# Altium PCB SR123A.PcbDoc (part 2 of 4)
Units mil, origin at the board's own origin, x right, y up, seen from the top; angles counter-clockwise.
Board outline 5500 x 3200 mil, 4 copper layers (Top Layer, Signal Layer 1, Signal Layer 2, Bottom Layer), stack 64.312 mil thick; 295 components, 105 nets, 659 pads, 1365 vias.
Unrouted connection lines stored in the file: 735.
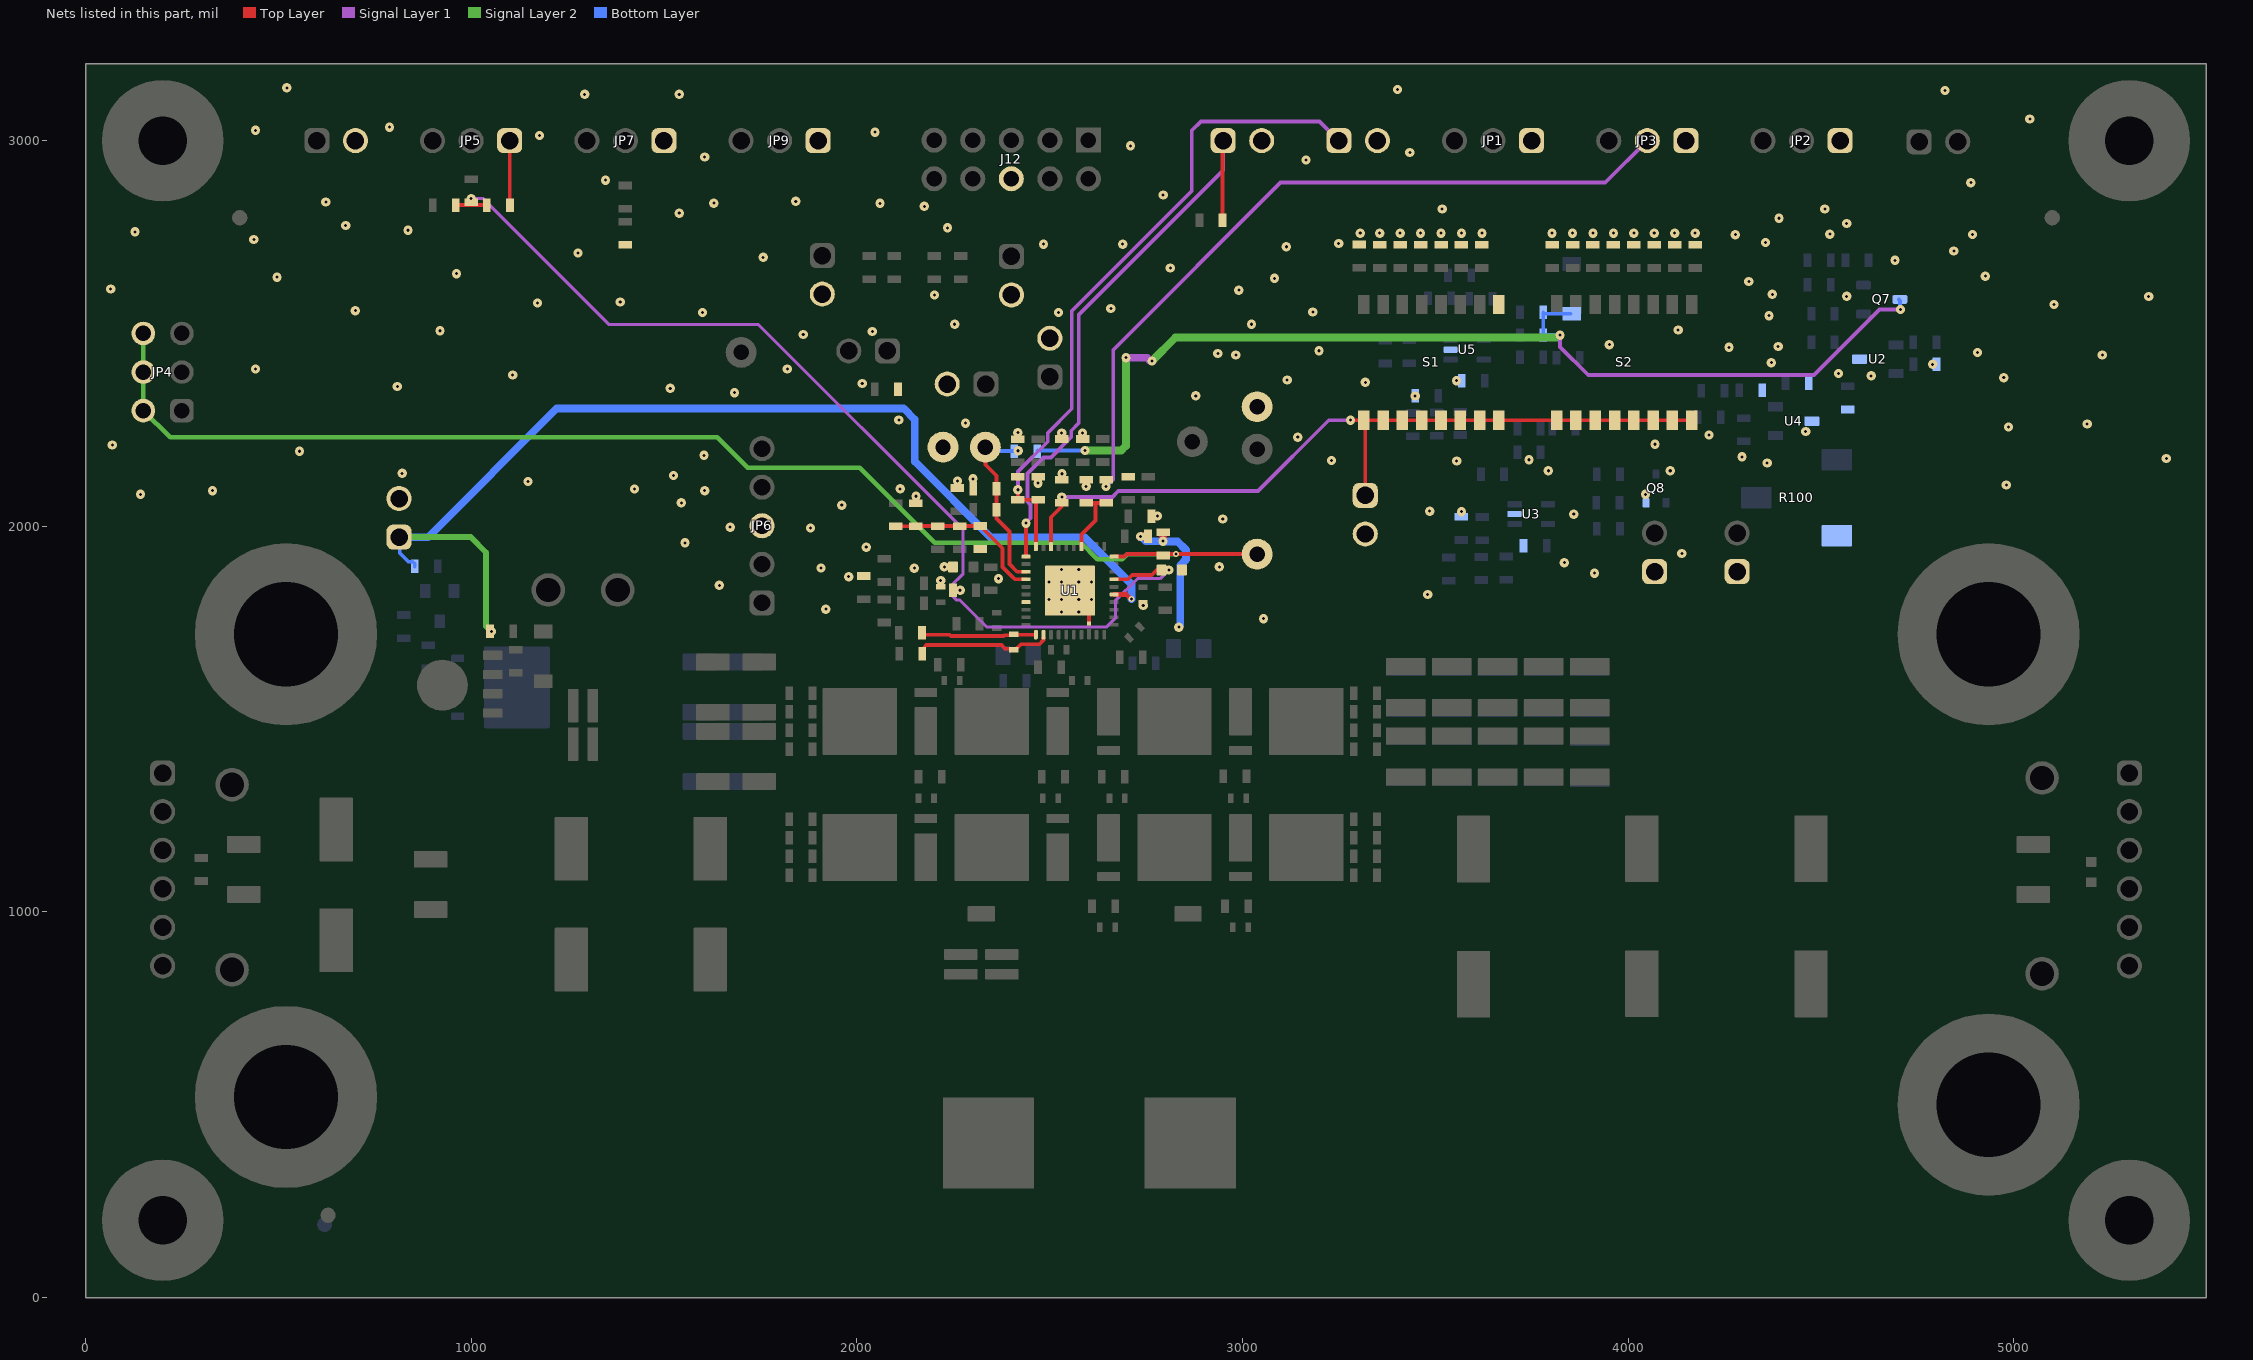
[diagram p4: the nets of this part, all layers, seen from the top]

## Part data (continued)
C27 C28 C29: library part CMP-0097021-1, "120 µF 50 V Aluminum - Polymer Capacitors Radial, Can - SMD 24mOhm 2000 Hrs @ 125°C", Digikey Part Number=399-A768MS127M1HLAE024CT-ND, Leakage Current=1200uA, Manufacturer=KEMET, Mouser Part Number=80-A768MS127M1HLAE24, Operating Temperature Range="-55°C to +125°C", Tolerance_%=20%, ValueDisplayed=120uF
C33 C46 C47: library part CMP-0086535-1, "0.1µF ±10% 50V Ceramic Capacitor X8L 0603 (1608 Metric)", Manufacturer="Murata Electronics North America", TempCo=-40+15%, Tolerance_%=10%
C34 C35: library part CMP-0006618-2, "CAP, CERM, 0.1 uF, 100 V, +/- 10%, X5R, 0402", Cap_Case=0402, Manufacturer=MuRata, Supplier Part Number 1=490-10458-1-ND, TempCo=X5R, Tolerance_%=10%, Value1=Unknown, Value2=100V, ValueDisplayed=0.1uF
C36: library part CMP-0007099-4, "CAP, CERM, 0.1 uF, 100 V, +/- 10%, X7S, AEC-Q200 Grade 1, 0603", Cap_Case=0603, Manufacturer=TDK, Supplier Part Number 1=445-6938-1-ND, TempCo=X7S, Tolerance_%=10%, Value1="0.04959 ohm", Value2=100V, ValueDisplayed=0.1uF
C37 C38: library part CMP-0092433-2, "Multi-Layer Ceramic Capacitor 22uF 10V X5R ±20% 0603 Paper T/R", Manufacturer=Murata, Operating Temperature Range="-55°C to +85°C", TempCo=15%, Temperature Characteristic=X5R, Tolerance_%=20%, ValueDisplayed=22uF
C39 C40: library part CMP-0006356-2, "CAP, CERM, 0.1 uF, 50 V, +/- 10%, X7R, AEC-Q200 Grade 1, 0402", Cap_Case=0402, Manufacturer=MuRata, Supplier Part Number 1=490-10672-1-ND, TempCo=X7R, Tolerance_%=10%, Value1=Unknown, Value2=50V, ValueDisplayed=0.1uF
C41: library part CMP-0006792-4, "CAP, CERM, 56 pF, 50 V, +/- 1%, C0G/NP0, 0603", Cap_Case=0603, Manufacturer=AVX, Supplier Part Number 1=478-7922-1-ND, TempCo=C0G/NP0, Tolerance_%=1%, Value1=Unknown, Value2=50V, ValueDisplayed=56pF
C42: library part CMP-0006984-4, "CAP, CERM, 0.022 uF, 50 V, +/- 10%, X7R, 0603", Cap_Case=0603, Manufacturer=Kemet, Supplier Part Number 1=399-5340-1-ND, TempCo=X7R, Tolerance_%=10%, Value1=Unknown, Value2=50V, ValueDisplayed=0.022uF
C43: library part CMP-0006793-4, "CAP, CERM, 56 pF, 50 V, +/- 5%, C0G/NP0, 0603", Cap_Case=0603, Manufacturer=AVX, Supplier Part Number 1=478-1172-1-ND, TempCo=C0G/NP0, Tolerance_%=5%, Value1="0.159 ohm", Value2=50V, ValueDisplayed=56pF
C44: library part CMP-0006806-4, "CAP, CERM, 0.033 uF, 50 V, +/- 5%, X7R, 0603", Cap_Case=0603, Manufacturer=AVX, Supplier Part Number 1=478-3723-1-ND, TempCo=X7R, Tolerance_%=5%, Value1=Unknown, Value2=50V, ValueDisplayed=0.033uF
C45: library part CMP-0007117-4, "CAP, CERM, 33 pF, 50 V, +/- 5%, C0G/NP0, 0603", Cap_Case=0603, Manufacturer="Samsung Electro-Mechanics", Supplier Part Number 1=1276-2262-1-ND, TempCo=C0G/NP0, Tolerance_%=5%, Value1=Unknown, Value2=50V, ValueDisplayed=33pF
C48: library part CMP-0006410-2, "CAP, CERM, 100 pF, 50 V, +/- 5%, C0G/NP0, 0402", Cap_Case=0402, Manufacturer=MuRata, Supplier Part Number 1=81-GRM1555C1H101JA1D, TempCo=C0G/NP0, Tolerance_%=5%, Value1=Unknown, Value2=50V, ValueDisplayed=100pF
C49: library part CMP-0860983-1, "CAP, CERM, 0.1 µF, 50 V,+/- 10%, X7R, 0402", Cap_Case=0402, Manufacturer="Passive Plus", TempCo=X7R, Tolerance_%=10%, Value2=50V, ValueDisplayed=0.1µF
C50: library part CMP-0007253-4, "CAP, CERM, 20 pF, 100 V, +/- 5%, C0G/NP0, 0603", Cap_Case=0603, Manufacturer=MuRata, Supplier Part Number 1=490-1334-1-ND, TempCo=C0G/NP0, Tolerance_%=5%, Value1=Unknown, Value2=100V, ValueDisplayed=20pF
C51: library part CMP-0007185-4, "CAP, CERM, 150 pF, 50 V, +/- 5%, C0G/NP0, 0603", Cap_Case=0603, Manufacturer=MuRata, Supplier Part Number 1=490-1431-1-ND, TempCo=C0G/NP0, Tolerance_%=5%, Value1=Unknown, Value2=50V, ValueDisplayed=150pF
C52 C53 C54: library part CMP-0006723-4, "CAP, CERM, 1000 pF, 100 V, +/- 5%, X7R, 0603", Cap_Case=0603, Manufacturer=AVX, Supplier Part Number 1=478-3698-1-ND, TempCo=X7R, Tolerance_%=5%, Value1="0.276 ohm", Value2=100V, ValueDisplayed=1000pF
C55 C56 C57 C61 C62 C63: library part CMP-0086096-1, "CAP, CERM, 680 pF, 50 V,+/- 1%, C0G/NP0, AEC-Q200 Grade 1, 0402", Cap_Case=0402, Manufacturer=MuRata, TempCo=C0G/NP0, Tolerance_%=1%, Value2=50V, ValueDisplayed=680pF
C58 C64: library part CMP-0006692-2, "CAP, CERM, 4700 pF, 50 V, +/- 10%, X7R, 0402", Cap_Case=0402, Manufacturer=MuRata, Supplier Part Number 1=490-1308-1-ND, TempCo=X7R, Tolerance_%=10%, Value1=Unknown, Value2=50V, ValueDisplayed=4700pF
C59: library part CMP-0008176-2, "CAP, CERM, 680 pF, 100 V, +/- 5%, C0G/NP0, 0805", Cap_Case=0805, Manufacturer=MuRata, Supplier Part Number 1=490-1613-1-ND, TempCo=C0G/NP0, Tolerance_%=5%, Value1=Unknown, Value2=100V, ValueDisplayed=680pF
C60: library part CMP-0008116-2, "CAP, CERM, 3000 pF, 100 V, +/- 5%, C0G/NP0, 0805", Cap_Case=0805, Manufacturer=MuRata, Supplier Part Number 1=GRM2165C2A302JA01D-ND, TempCo=C0G/NP0, Tolerance_%=5%, Value1=Unknown, Value2=100V, ValueDisplayed=3000pF
C89 C91 C95: library part CMP-0006889-4, "CAP, CERM, 0.018 uF, 100 V, +/- 10%, X7R, 0603", Cap_Case=0603, Manufacturer=Kemet, Supplier Part Number 1=399-3475-1-ND, TempCo=X7R, Tolerance_%=10%, Value1=Unknown, Value2=100V, ValueDisplayed=0.018uF
C90 C92 C94: library part CMP-0006979-5, "CAP, CERM, 0.1 uF, 25 V, +/- 10%, X7R, 0603", Cap_Case=0603, Manufacturer=Kemet, Supplier Part Number 1=399-5345-1-ND, TempCo=X7R, Tolerance_%=10%, Value1=Unknown, Value2=25V, ValueDisplayed=0.1uF
C93: library part CMP-0085855-1, "CAP, CERM, 10 µF, 10 V,+/- 10%, X5R, 0603", Cap_Case=0603, Manufacturer=MuRata, TempCo=X5R, Tolerance_%=10%, Value2=10V, ValueDisplayed=10µF
D1: library part CMP-0005740-3, "Diode, Zener, 10 V, 500 mW, SOD-123", Manufacturer="ON Semiconductor", Power_W=500mW, Value1=0.5W
D2: library part CMP-0096356-1, "Diode Array 1 Pair Series Connection Schottky 70 V 200mA (DC) Surface Mount TO-236-3, SC-59, SOT-23-3", Digikey Part Number=BAS70-04-E3-18GICT-ND, Forward Current=200mA, Manufacturer=Vishay, Max Surge Forward Current=600mA, Mouser Part Number=78-BAS70-04-E3-18, Operating Temperature Range="-55°C to +125°C", Peak Reverse Current=0.02uA, ValueDisplayed=1.5pF
D3: library part CMP-0028457-2, "Diode, Schottky, 30 V, 0.2 A, SOD-123", Manufacturer="ON Semiconductor", Value1=0.2A, Value2=0.8V
FID1 FID2 FID3 FID4 FID5 FID6: library part CMP-0077181-1, "Fiducial mark.  There is nothing to buy or mount.", Manufacturer=N/A
H1 H2 H3 H4: library part CMP-0003617-1, "Machine Screw, Round, #4-40 x 1/4, Nylon, Philips panhead", Manufacturer="B&F Fastener Supply", Supplier Part Number 1=H542-ND
H5 H6 H7 H8: library part CMP-0003610-1, "Standoff, Hex, 0.5\"L #4-40 Nylon", Manufacturer=Keystone, Supplier Part Number 1=36-1902C-ND
J1 J2 J3 J4: library part CMP-0055387-2, "Standard Banana Jack, Uninsulated, 15A", Manufacturer="Cinch Connectivity", Supplier Part Number 1=J147-ND
J5 J6: library part CMP-0054801-2, "Header, 2.54 mm, 6x1, Gold, TH", Color=Black, Manufacturer="Wurth Elektronik", Supplier Part Number 1=732-5319-ND
J7 J8 J9 J10 J11 J13 J14 J15 J16 JP8 JP10 JP11 JP12: library part CMP-0054794-2, "Header, 2.54 mm, 2x1, Gold, TH", Color=Black, Manufacturer="Wurth Elektronik", Supplier Part Number 1=732-5315-ND
J12: library part CMP-0055448-2, "Header (shrouded), 100mil, 5x2, High-Temperature, Gold, TH", Manufacturer=3M, Supplier Part Number 1=MHC10K-ND
JP1 JP2 JP3 JP5 JP7 JP9: library part CMP-0054796-4, "Header, 2.54 mm, 3x1, Gold, TH", Manufacturer="Wurth Elektronik", Supplier Part Number 1=732-5316-ND
JP4: library part CMP-0055587-2, "Header, 2.54mm, 3x2, Gold, TH", Color=Natural, Manufacturer=Samtec, Supplier Part Number 1=HTSW-103-07-G-D-ND
JP6: library part CMP-0084909-1, "Header, 2.54mm, 5x1, Gold, TH", Color=Black, Current_A=3A, Manufacturer="Wurth Elektronik", Voltage_V=250V
L1: library part CMP-0064042-1, "Inductor, Shielded Drum Core, WE-Superflux200, 2.6 uH, 31.5 A, 0.0016 ohm, SMD", Manufacturer="Wurth Elektronik", Supplier Part Number 1=732-2170-1-ND, Value1="0.0016 ohm", Value2=31.5A, ValueDisplayed=2.6uH
Logo3: library part CMP-0074847-1, "FCC_disclaimer"
Logo4: library part CMP-0074769-4, Manufacturer="Texas Instruments"
Logo5 Logo6: library part CMP-0074837-2, "IEC 61010-1 Hot Surface Warning", Manufacturer="Texas Instruments"
NT1: library part CMP-0078142-6, "Single point connection between nets.", Manufacturer=N/A
Q1 Q1A Q2 Q2A Q3 Q3A Q4 Q4A: library part CMP-0124204-1, "N-Channel 40 V 120A Surface Mount PG-TDSON-8-34", Digikey Part Number=448-IAUCN04S7L014ATMA1CT-ND, Drain To Source Breakdown Voltage=40V, Input Capacitance At Vds="2424pF @ 20V", Manufacturer=Infineon, Mouser Part Number=726-IAUCN04S7L014ATM, Operating Temperature Range="-55°C to +175°C", Power_W=88W, Pulse Drain Current=500A, Typ Forward Diode Voltage=0.8V
Q5: library part CMP-0098297-1, "Trans MOSFET P-CH -40V -100A 8-Pin SOIC - Tape and Reel", Digikey Part Number=SI7155DP-T1-GE3CT-ND, Drain To Source Breakdown Voltage=-40V, Input Capacitace At Vds="12900pF @ -20V", Manufacturer=Vishay, Mouser Part Number=78-SI7155DP-T1-GE3, Operating Temperature Range="-55°C to +150°C", Power_W=6.25W, Pulse Drain Current=-200A, Typ Forward Diode Voltage=-0.73V
Q6: library part CMP-0000823-2, "MOSFET, N-CH, 60 V, 100 A, DNK0008A (VSON-CLIP-8)", Alternate Manufacturer=None, Manufacturer="Texas Instruments", Supplier Part Number 1=296-41076-1-ND, Value1=0.003, Value2="41 nC"
Q7: library part CMP-0000367-2, "Transistor, PNP, 45 V, 0.5 A, AEC-Q101, SOT-23", Manufacturer="ON Semiconductor", Supplier Part Number 1=BC807-40LT1GOSCT-ND, Value1="0.5 A", Value2=600
Q8: library part CMP-0000776-1, "MOSFET, N-CH, 60 V, 0.115 A, SOT-323", Alternate Manufacturer=None, Manufacturer="Diodes Inc.", Supplier Part Number 1=2N7002W-FDICT-ND, Value1=7
R1 R2: library part CMP-0095678-1, "4 mOhms ±1% 1W Chip Resistor Wide 0805 (2012 Metric), 0508 Automotive AEC-Q200, Current Sense Metal Foil", Digikey Part Number=408-1594-1-ND, Manufacturer=Susumu, Mouser Part Number=754-KRL2012EMR004FT5, Operating Temperature Range="-55°C to +155°C", Power_W=1W, TempCo=50ppm/°C, Tolerance_%=1%
R3 R4: library part CMP-0090631-1, "3 mOhms ±1% 1W Chip Resistor Wide 0805 (2012 Metric), 0508 Automotive AEC-Q200, Current Sense Metal Foil", Digikey Part Number=408-1593-1-ND, Manufacturer=Susumu, Mouser Part Number=754-KRL2012EMR003FT5, Operating Temperature Range="-55°C to +155°C", Power_W=1W, TempCo=50ppm/°C, Tolerance_%=1%
R5 R6 R11 R12 R14 R16 R18 R22 R23 R24 R25 R34 R35 R36 R37 R56 R57 R61 R62 R66 R67 R68 R75 R85 R91: library part CMP-0023343-3, "RES, 0, 1%, 0.1 W, AEC-Q200 Grade 0, 0603", Manufacturer="Stackpole Electronics Inc", Power_W=100mW, Supplier Part Number 1=RMCF0603ZT0R00CT-ND, TempCo=ppm/C, Tolerance_%=1%, Value2=0.1W, Value_Code=0
R7 R8: library part CMP-0022004-4, "RES, 10.0, 1%, 0.25 W, AEC-Q200 Grade 0, 0603", Manufacturer=Vishay-Dale, Power_W=250mW, Supplier Part Number 1=541-10.0SCT-ND, TempCo="100 ppm/C", Tolerance_%=1%, Value2=0.25W, Value_Code=10R0, ValueDisplayed=10.0
R9 R20: library part CMP-0023292-5, "RES, 82.0 k, 1%, 0.1 W, 0603", Manufacturer=Yageo, Power_W=100mW, Supplier Part Number 1=311-82.0KHRCT-ND, TempCo="100 ppm/C", Tolerance_%=1%, Value2=0.1W, Value_Code=82k0, ValueDisplayed=82.0k
R10 R21: library part CMP-0022600-4, "RES, 7.32 k, 1%, 0.1 W, AEC-Q200 Grade 0, 0603", Manufacturer=Vishay-Dale, Power_W=100mW, Supplier Part Number 1=541-7.32KHCT-ND, TempCo="100 ppm/C", Tolerance_%=1%, Value2=0.1W, Value_Code=7k32, ValueDisplayed=7.32k
R13 R63: library part CMP-0022732-2, "RES, 2.00, 1%, 0.125 W, 0603", Manufacturer=Vishay/Beyschlag, Power_W=125mW, Supplier Part Number 1=MCT06030C2008FP500-ND, TempCo="50 ppm/C", Tolerance_%=1%, Value2=0.125W, Value_Code=2R00, ValueDisplayed=2.00
R15: library part CMP-0023267-5, "RES, 75.0 k, 1%, 0.1 W, 0603", Manufacturer=Yageo, Power_W=100mW, Supplier Part Number 1=311-75.0KHRCT-ND, TempCo="100 ppm/C", Tolerance_%=1%, Value2=0.1W, Value_Code=75k0, ValueDisplayed=75.0k
R17: library part CMP-0022106-4, "RES, 19.6 k, 1%, 0.1 W, AEC-Q200 Grade 0, 0603", Manufacturer=Vishay-Dale, Power_W=100mW, Supplier Part Number 1=541-19.6KHCT-ND, TempCo="100 ppm/C", Tolerance_%=1%, Value2=0.1W, Value_Code=19k6, ValueDisplayed=19.6k
R19 R72 R76: library part CMP-0022751-4, "RES, 10.0, 1%, 0.1 W, 0603", Manufacturer=Yageo, Power_W=100mW, Supplier Part Number 1=311-10.0HRCT-ND, TempCo="100 ppm/C", Tolerance_%=1%, Value2=0.1W, Value_Code=10R0, ValueDisplayed=10.0
R26: library part CMP-0023975-2, "RES, 23.4 k, 0.1%, 0.1 W, 0603", Manufacturer="Yageo America", Power_W=100mW, TempCo="25 ppm/C", Tolerance_%=0.1%, Value2=0.1W, Value_Code=23k4, ValueDisplayed=23.4k
R27 R29 R47: library part CMP-0023307-5, "RES, 8.25 k, 1%, 0.1 W, 0603", Manufacturer=Yageo, Power_W=100mW, Supplier Part Number 1=311-8.25KHRCT-ND, TempCo="100 ppm/C", Tolerance_%=1%, Value2=0.1W, Value_Code=8k25, ValueDisplayed=8.25k
R28 R44: library part CMP-0022381-4, "RES, 3.83 k, 1%, 0.1 W, AEC-Q200 Grade 0, 0603", Manufacturer=Vishay-Dale, Power_W=100mW, Supplier Part Number 1=541-3.83KHCT-ND, TempCo="100 ppm/C", Tolerance_%=1%, Value2=0.1W, Value_Code=3k83, ValueDisplayed=3.83k
R30: library part CMP-0022597-4, "RES, 78.7 k, 1%, 0.1 W, AEC-Q200 Grade 0, 0603", Manufacturer=Vishay-Dale, Power_W=100mW, Supplier Part Number 1=541-78.7KHCT-ND, TempCo="100 ppm/C", Tolerance_%=1%, Value2=0.1W, Value_Code=78k7, ValueDisplayed=78.7k
R31: library part CMP-0024307-2, "RES, 50.5 k, 0.1%, 0.1 W, 0603", Manufacturer="Yageo America", Power_W=100mW, TempCo="25 ppm/C", Tolerance_%=0.1%, Value2=0.1W, Value_Code=50k5, ValueDisplayed=50.5k
R32 R48: library part CMP-0022000-4, "RES, 10.5 k, 1%, 0.1 W, AEC-Q200 Grade 0, 0603", Manufacturer=Vishay-Dale, Power_W=100mW, Supplier Part Number 1=541-10.5KHCT-ND, TempCo="100 ppm/C", Tolerance_%=1%, Value2=0.1W, Value_Code=10k5, ValueDisplayed=10.5k
R33 R86 R87 R89 R90: library part CMP-0023653-3, "RES, 10.0 k, 0.1%, 0.1 W, 0603", Manufacturer="Yageo America", Power_W=100mW, TempCo="25 ppm/C", Tolerance_%=0.1%, Value2=0.1W, Value_Code=10k0, ValueDisplayed=10.0k
R38: library part CMP-0025810-4, "RES, 43 k, 5%, 0.1 W, AEC-Q200 Grade 0, 0603", Manufacturer=Vishay-Dale, Power_W=100mW, Supplier Part Number 1=541-43KGCT-ND, TempCo="200 ppm/C", Tolerance_%=5%, Value2=0.1W, Value_Code=43k0, ValueDisplayed=43k
R39: library part CMP-0025725-4, "RES, 180 k, 5%, 0.1 W, AEC-Q200 Grade 0, 0603", Manufacturer=Vishay-Dale, Power_W=100mW, Supplier Part Number 1=541-180KGCT-ND, TempCo="200 ppm/C", Tolerance_%=5%, Value2=0.1W, Value_Code=180k
R40: library part CMP-0022481-5, "RES, 511, 1%, 0.1 W, AEC-Q200 Grade 0, 0603", Manufacturer=Vishay-Dale, Power_W=100mW, Supplier Part Number 1=541-511HCT-ND, TempCo="100 ppm/C", Tolerance_%=1%, Value2=0.1W, Value_Code=511R, ValueDisplayed=511
R41: library part CMP-0022115-4, "RES, 1.15 k, 1%, 0.1 W, AEC-Q200 Grade 0, 0603", Manufacturer=Vishay-Dale, Power_W=100mW, Supplier Part Number 1=541-1.15KHCT-ND, TempCo="100 ppm/C", Tolerance_%=1%, Value2=0.1W, Value_Code=1k15, ValueDisplayed=1.15k
R42: library part CMP-0022891-5, "RES, 1.87 k, 1%, 0.1 W, 0603", Manufacturer=Yageo, Power_W=100mW, Supplier Part Number 1=311-1.87KHRCT-ND, TempCo="100 ppm/C", Tolerance_%=1%, Value2=0.1W, Value_Code=1k87, ValueDisplayed=1.87k
R43: library part CMP-0022996-5, "RES, 2.70 k, 1%, 0.1 W, 0603", Manufacturer=Yageo, Power_W=100mW, Supplier Part Number 1=311-2.70KHRCT-ND, TempCo="100 ppm/C", Tolerance_%=1%, Value2=0.1W, Value_Code=2k70, ValueDisplayed=2.70k
R45 R58: library part CMP-0023198-5, "RES, 5.10 k, 1%, 0.1 W, 0603", Manufacturer=Yageo, Power_W=100mW, Supplier Part Number 1=311-5.10KHRCT-ND, TempCo="100 ppm/C", Tolerance_%=1%, Value2=0.1W, Value_Code=5k10, ValueDisplayed=5.10k
R46: library part CMP-0023250-5, "RES, 6.49 k, 1%, 0.1 W, 0603", Manufacturer=Yageo, Power_W=100mW, Supplier Part Number 1=311-6.49KHRCT-ND, TempCo="100 ppm/C", Tolerance_%=1%, Value2=0.1W, Value_Code=6k49, ValueDisplayed=6.49k
R49: library part CMP-0022790-5, "RES, 13.3 k, 1%, 0.1 W, 0603", Manufacturer=Yageo, Power_W=100mW, Supplier Part Number 1=311-13.3KHRCT-ND, TempCo="100 ppm/C", Tolerance_%=1%, Value2=0.1W, Value_Code=13k3, ValueDisplayed=13.3k
R50: library part CMP-0022079-4, "RES, 16.2 k, 1%, 0.1 W, AEC-Q200 Grade 0, 0603", Manufacturer=Vishay-Dale, Power_W=100mW, Supplier Part Number 1=541-16.2KHCT-ND, TempCo="100 ppm/C", Tolerance_%=1%, Value2=0.1W, Value_Code=16k2, ValueDisplayed=16.2k
R51: library part CMP-0022905-5, "RES, 20.5 k, 1%, 0.1 W, 0603", Manufacturer=Yageo, Power_W=100mW, Supplier Part Number 1=311-20.5KHRCT-ND, TempCo="100 ppm/C", Tolerance_%=1%, Value2=0.1W, Value_Code=20k5, ValueDisplayed=20.5k
R52: library part CMP-0022237-4, "RES, 24.9 k, 1%, 0.1 W, AEC-Q200 Grade 0, 0603", Manufacturer=Vishay-Dale, Power_W=100mW, Supplier Part Number 1=541-24.9KHCT-ND, TempCo="100 ppm/C", Tolerance_%=1%, Value2=0.1W, Value_Code=24k9, ValueDisplayed=24.9k
R53: library part CMP-0022324-4, "RES, 30.1 k, 1%, 0.1 W, AEC-Q200 Grade 0, 0603", Manufacturer=Vishay-Dale, Power_W=100mW, Supplier Part Number 1=541-30.1KHCT-ND, TempCo="100 ppm/C", Tolerance_%=1%, Value2=0.1W, Value_Code=30k1, ValueDisplayed=30.1k
R54: library part CMP-0022352-4, "RES, 35.7 k, 1%, 0.1 W, AEC-Q200 Grade 0, 0603", Manufacturer=Vishay-Dale, Power_W=100mW, Supplier Part Number 1=541-35.7KHCT-ND, TempCo="100 ppm/C", Tolerance_%=1%, Value2=0.1W, Value_Code=35k7, ValueDisplayed=35.7k
R55: library part CMP-0025771-4, "RES, 2.7 k, 5%, 0.1 W, AEC-Q200 Grade 0, 0603", Manufacturer=Vishay-Dale, Power_W=100mW, Supplier Part Number 1=541-2.7KGCT-ND, TempCo="200 ppm/C", Tolerance_%=5%, Value2=0.1W, Value_Code=2k70, ValueDisplayed=2.7k
R59 R60: library part CMP-0025804-4, "RES, 3.0, 5%, 0.1 W, AEC-Q200 Grade 0, 0603", Manufacturer=Vishay-Dale, Power_W=100mW, Supplier Part Number 1=541-3.0GCT-ND, TempCo="200 ppm/C", Tolerance_%=5%, Value2=0.1W, Value_Code=3R00, ValueDisplayed=3.0
R64 R65: library part CMP-0023000-5, "RES, 2.00 k, 1%, 0.1 W, 0603", Manufacturer=Yageo, Power_W=100mW, Supplier Part Number 1=311-2.00KHRCT-ND, TempCo="100 ppm/C", Tolerance_%=1%, Value2=0.1W, Value_Code=2k00, ValueDisplayed=2.00k
R69: library part CMP-0022735-5, "RES, 100 k, 1%, 0.1 W, 0603", Manufacturer=Yageo, Power_W=100mW, Supplier Part Number 1=311-100KHRCT-ND, TempCo="100 ppm/C", Tolerance_%=1%, Value2=0.1W, Value_Code=100k
R70: library part CMP-0023153-5, "RES, 4.70 k, 1%, 0.1 W, 0603", Manufacturer=Yageo, Power_W=100mW, Supplier Part Number 1=311-4.70KHRCT-ND, TempCo="100 ppm/C", Tolerance_%=1%, Value2=0.1W, Value_Code=4k70, ValueDisplayed=4.70k
R71 R73 R74 R83 R98: library part CMP-0021998-4, "RES, 10.0 k, 1%, 0.1 W, AEC-Q200 Grade 0, 0603", Manufacturer=Vishay-Dale, Power_W=100mW, Supplier Part Number 1=541-10.0KHCT-ND, TempCo="100 ppm/C", Tolerance_%=1%, Value2=0.1W, Value_Code=10k0, ValueDisplayed=10.0k
R77 R78 R79 R92 R93 R94: library part CMP-0023132-5, "RES, 47.5 k, 1%, 0.1 W, 0603", Manufacturer=Yageo, Power_W=100mW, Supplier Part Number 1=311-47.5KHRCT-ND, TempCo="100 ppm/C", Tolerance_%=1%, Value2=0.1W, Value_Code=47k5, ValueDisplayed=47.5k
R80 R95: library part CMP-0022982-5, "RES, 2.15 k, 1%, 0.1 W, 0603", Manufacturer=Yageo, Power_W=100mW, Supplier Part Number 1=311-2.15KHRCT-ND, TempCo="100 ppm/C", Tolerance_%=1%, Value2=0.1W, Value_Code=2k15, ValueDisplayed=2.15k
R81 R82 R96 R97: library part CMP-0025899-5, "RES, 1.0 k, 5%, 0.1 W, 0603", Manufacturer=Yageo, Power_W=100mW, Supplier Part Number 1=311-1.0KGRCT-ND, TempCo="100 ppm/C", Tolerance_%=5%, Value2=0.1W, Value_Code=1k00, ValueDisplayed=1.0k
R84 R99: library part CMP-0022808-4, "RES, 150 k, 1%, 0.1 W, 0603", Manufacturer=Yageo, Power_W=100mW, Supplier Part Number 1=311-150KHRCT-ND, TempCo="100 ppm/C", Tolerance_%=1%, Value2=0.1W, Value_Code=150k
R88: library part CMP-0023080-5, "RES, 3.32 k, 1%, 0.1 W, 0603", Manufacturer=Yageo, Power_W=100mW, Supplier Part Number 1=311-3.32KHRCT-ND, TempCo="100 ppm/C", Tolerance_%=1%, Value2=0.1W, Value_Code=3k32, ValueDisplayed=3.32k
R100: library part CMP-0092665-1, "10 kOhms 0.25W, 1/4W Gull Wing Surface Mount Trimmer Potentiometer Cermet 14.0 Turn Top Adjustment", Digikey Part Number=ST5ETW103CT-ND, Manufacturer="Nidec Copal Electronics", Mouser Part Number=229-ST-5ETW103, Operating Temperature Range="-55°C to +120°C", Power_W=0.25W, TempCo=100ppm/°C, Tolerance_%=10%
S1 S2: library part CMP-0002229-1, "Switch, SPST, 8 Pos, 25mA, 24VDC, SMD", CurrentRating_mA=25A, Manufacturer="CTS Electrocomponents", Supplier Part Number 1=CT2188LPST-ND
SH-JP1 SH-JP2 SH-JP3 SH-JP4 SH-JP5 SH-JP6 SH-JP7 SH-JP8 SH-JP9 SH-JP10 SH-JP11 SH-JP12: library part CMP-0078738-1, "Single Operation 2.54mm Pitch Open Top Jumper Socket", Manufacturer=Harwin, Supplier Part Number 1=952-2881-ND
TP1 TP2: library part CMP-0055147-2, "Test Point, Multipurpose, Red, TH", Color=Red, Manufacturer="Keystone Electronics", Supplier Part Number 1=36-5010-ND
TP3 TP4: library part CMP-0055148-2, "Test Point, Multipurpose, Black, TH", Color=Black, Manufacturer="Keystone Electronics", Supplier Part Number 1=36-5011-ND
TP5 TP6: library part CMP-0067619-1, "Natural PC Test Point Brass, SMT", Manufacturer=Harwin, Supplier Part Number 1=952-2665-1-ND
TP7 TP8: library part CMP-0055150-2, "Test Point, Multipurpose, Orange, TH", Color=Orange, Manufacturer="Keystone Electronics", Supplier Part Number 1=36-5013-ND
TP9 TP14: library part CMP-0055138-2, "Test Point, Miniature, Black, TH", Color=Black, Manufacturer="Keystone Electronics", Supplier Part Number 1=36-5001-ND
TP10 TP11 TP12 TP13 TP15: library part CMP-0055141-2, "Test Point, Miniature, Yellow, TH", Color=Yellow, Manufacturer="Keystone Electronics", Supplier Part Number 1=36-5004-ND
U1: library part CMP-0124597-1, "48-V 4 Switch Buck-Boost Controller with I2C interface", Manufacturer="Texas Instruments", Max Supply Voltage=48V, Min Supply Voltage=3.3V, Nominal Supply Current=25uA, Operating Temperature Range="-40°C to +150°C", Output Voltage=3.3-48V, Switching Frequency=100-2200kHz
U2 U4: library part CMP-0032976-1, "Low Voltage Adjustable Precision Shunt Regulator, 39 ppm / degC, 15 mA, -40 to 85 degC, 3-pin SOT-23 (DBZ), Green (RoHS & no Sb/Br)", Manufacturer="Texas Instruments", Rating=Catalog, Temp Coeff(Max)(ppm/ degree C)=129, Temp Coeff(Typ)(ppm/ degree C)=39
U3: library part CMP-0122166-1, "Single low-voltage comparator with push-pull output 5-SC70 -40 to 125", Digikey Part Number=296-TLV9030DCKRCT-ND, Input Bias Current=0.000005uA, Input Offset Voltage=0.3mV, Manufacturer="Texas Instruments", Max Supply Voltage=5.5V, Min Supply Voltage=1.65V, Mouser Part Number=595-TLV9030DCKR, Nominal Supply Current=17.1uA, Operating Temperature Range="-40°C to +125°C", Output Current Per Channel=100mA, Voltage Gain=200V/mV
U5: library part CMP-0033571-1, "Single, 5.5-V, 3-MHz high-output-current (150 mA) fast-shutdown (1 μs) operational amplifier 5-SC70 -40 to 125", Digikey Part Number=296-OPA310IDCKRCT-ND, Input Bias Current=0.000001uA, Input Offset Voltage=0.25mV, Manufacturer="Texas Instruments", Max Dual Supply Voltage=2.75V, Max Supply Voltage=5.5V, Min Dual Supply Voltage=750mV, Min Supply Voltage=1.5V, Mouser Part Number=595-OPA310IDCKR, Nominal Supply Current=165uA, Operating Temperature Range="-40°C to +125°C", Output Current Per Channel=20mA, Voltage Gain=125dB
ZZ2: library part CMP-0077236-1
ZZ3: library part CMP-0077237-1
ZZ4: library part CMP-0077238-1

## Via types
v1: diameter 24, hole 7.87, Top Layer to Bottom Layer, tented both sides, 520 vias
v2: diameter 16, hole 8, Top Layer to Bottom Layer, tented both sides, 418 vias
v3: diameter 24, hole 8, Top Layer to Bottom Layer, tented both sides, 412 vias
v4: diameter 19.68, hole 7.87, Top Layer to Bottom Layer, tented both sides, 12 vias
v5: diameter 16, hole 7.87, Top Layer to Bottom Layer, tented both sides, 2 vias
v6: diameter 34, hole 16, Top Layer to Bottom Layer, tented both sides, 1 vias

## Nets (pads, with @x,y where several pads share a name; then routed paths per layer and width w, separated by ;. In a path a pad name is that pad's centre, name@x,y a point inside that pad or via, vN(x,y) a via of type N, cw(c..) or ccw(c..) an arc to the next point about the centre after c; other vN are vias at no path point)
AGND: C34.1 C35.2 C36.1 C37.1 C41.2 C42.2 C43.2 C44.2 C45.2 C46.2 C47.2 C51.2 C52.2 C53.2 C54.2 C90.2 C92.2 C93.2 C94.2 J7.2 J8.2 J9.2 J10.2 J11.2 J12.6 J14.2 J15.1 J16.1 JP1.1 JP2.1 JP3.1 JP5.1 JP6.3 JP7.1 JP8.2 JP9.1 JP11.2 JP12.2 NT1.2 Q8.2 R10.1 R17.1 R21.1 R26.1 R29.1 R30.1 R31.1 R40.1 R41.1 R42.1 R43.1 R44.1 R45.1 R46.1 R47.1 R48.1 R49.1 R50.1 R51.1 R52.1 R53.1 R54.1 R55.1 R57.2 R70.1 R80.1 R90.2 R95.1 R100.3 S1.1 TP9.1 TP14.1 U1.17 U1.41 U2.3 U3.2 U4.3 U5.2 | length 637.4
  Top Layer w10: R17.1@1100,2832.68 JP5.1@1100,3000 JP5.1@1100,3005.59 ; R30.1@2417.7,2226.09 v1(2417.7,2242.78) ; v1(2469.92,2111.69) 2469.92,2128.38 R31.1@2470.26,2128.72 ; R55.1@2531.4,2120.8 2531.4,2135.12 v1(2532.47,2136.2) ; NT1.2@2602.22,1748.34 U1.41@2602.22,1777.88 ; C34.1@2742.37,1801.95 2742.89,1801.43 v1(2742.89,1794.39)
  Top Layer w20: v1(2736.27,1973.26) v1@2744.74,1973.26 ; v1(2794.32,1961.47) C36.1@2794.32,1980.94
  Bottom Layer w10: v1@2785.32,1961.47 v1@2789.82,1956.97 ; v1@2794.32,1956.97 2794.32,1960.82 v1(2794.32,1961.47)
  Bottom Layer w20: v1@2734.96,1971.95 2735.5,1972.49 2738.12,1972.49 2749.14,1961.47 v1@2792.47,1961.47 ; v1@2794.32,1960.82 2794.43,1960.71 2831.42,1960.71 2853.66,1938.47 2853.66,1913.73 2839.03,1899.11 2839.03,1743.57 2835,1739.54 v1(2835,1738.46)
  other v1: 3054.7,1760.48 1919.66,1785.08 3480.32,1823.13 2268.12,1834.12 1643.69,1846.89 2217.64,1859.28 2367.43,1864.12 1978.89,1869.36 3913,1878.43 2149.19,1891.48 1907.45,1891.69 2227.11,1894.88 2940,1895 3834.87,1905.51 4139.53,1929.27 2024.57,1945.95 1554.27,1957.1 1880,1995.26 1671.75,1997.74 2949,2018.96 2780.08,2026.62 3859.24,2031.51 3568.03,2037.81 3485.58,2039.08 1961.04,2054.59 1544.89,2060.75 2153.61,2077.87 142.76,2082.92 4045.57,2082.79 329.47,2092.38 1605.68,2092.38 1423.63,2096.98 2112.63,2097.1 2594.9,2103.69 4981,2107 1147.19,2116.01 2261.32,2117.3 2301.57,2123.05 1524.46,2131.42 821.05,2137.28 3793.41,2144.01 4109.45,2144.01 4360.85,2163.94 3555.59,2169.44 3231.3,2170.36 3743.14,2172.52 5396,2176 4295.82,2180.14 1603.56,2184.13 554.7,2194.57 69.5,2210.55 4069.71,2212.76 3143.53,2231 4210,2236.64 2531.21,2241.64 2585.06,2241.64 4460.77,2245.91 4986.36,2257.23 5190.55,2265.13 2282.15,2267.3 2108.95,2275.74 2879.03,2338.4 3448.03,2338 1683.03,2346.39 1516.34,2357.88 808.47,2362.16 2014.15,2370.46 3318.61,2373.33 3555.23,2377.5 3116.18,2379.61 4974.29,2385.25 4630.38,2390.21 1107.63,2392.53 4545.84,2395.94 441,2407.8 1820,2407.81 4790,2420 4371.45,2424.26 2983.05,2443.91 5230,2444 2936.19,2447.84 4906.36,2450.53 3198.64,2455.2 4261.99,2464.01 4389.34,2466.31 3951.54,2470.99 1861.22,2497.46 2040.36,2504.95 918.97,2507.03 4130,2509 2253.75,2523.87 3023.48,2523.87 4365.73,2546.2 1600,2554.43 2523.35,2554.43 3182.74,2555.6 699.61,2558.99 2658.69,2564.84 5104.35,2575.07 1172.1,2579.13 1386.67,2581.55 4566.89,2596.3 5350,2596 2201.71,2599.94 4374.21,2601.46 2990.7,2612.39 65.22,2615.39 4313.27,2635 3083.19,2643 496.54,2645.86 4926.56,2648.5 962,2655 2813,2670 4692.23,2689.58 1757.39,2697.35 1277.24,2708.96 4844.8,2713.85 3113.92,2724.83 2484.4,2731.6 2689.41,2731.6 3249.53,2733 4356.47,2736.11 436.5,2743.89 4278.31,2756.07 4893.06,2756.42 4523.2,2757.48 3305.61,2760 3356,2760 3409,2760 3462,2760 3515,2760 3568,2760 3621,2760 3803,2760 3856,2760 3909,2760 3962,2760 4015,2760 4068,2760 4121,2760 4174,2760 128.58,2763.57 836.53,2767.7 2235,2774 674.65,2780.22 4566.89,2785 4391.69,2798.8 1539.59,2812 3518.03,2822.95 4510.24,2822.95 2175.13,2829.79 1629.17,2837.92 2060.46,2837.53 623.09,2841.07 1841.75,2842.72 2794.66,2858.75 4888.99,2891.02 1348.32,2897.44 3165,2950 1605.68,2957.29 3434,2969 2710.03,2986.57 1177.24,3013.64 2047.48,3021.84 441,3026.64 788,3034.95 5042.03,3056.39 1294.41,3120 1539.59,3120 4822.07,3129.89 3402.03,3132.39 522,3137
  other v4: 2530.36,1777.88 2575.64,1777.88 2497.88,1810.36 2530.36,1810.36 2575.64,1810.36 2608.12,1810.36 2497.88,1855.64 2530.36,1855.64 2575.64,1855.64 2608.12,1855.64 2530.36,1888.12 2575.64,1888.12
BIAS: C36.2 JP4.2 JP4.4 JP4.6 TP15.1 U1.40 | length 3425.6
  Top Layer w10: U1.40@2667.17,1921.58 2694.94,1921.58 2701.15,1927.79 ; 2694.71,1921.36 2701.15,1927.75 2794.32,1927.75 2914.71,1927.75 2933.21,1927.75 2963.8,1927.75 3037.84,1927.75 TP15.1@3038,1927.91
  Signal Layer 2 w10: TP15.1@3037.84,1927.75 TP15.1@3038,1927.91
  Signal Layer 2 w12: JP4.6@150,2500 JP4.4@150,2400 JP4.2@150,2300 219.38,2230.62 1637.84,2230.62 1716.75,2151.71 2007.57,2151.71 2202.18,1957.1 2581.35,1957.1 2623.65,1914.8 2688.16,1914.8 2701.27,1927.91 2827.62,1927.91 v2(2827.78,1927.75)
CDC: C41.1 J14.1 R31.2 U1.10 | length 1732.6
  Top Layer w10: v3(2417.7,2094.66) 2417.93,2094.43 C41.1@2417.93,2068.72 R31.2@2470.26,2068.72 2464.42,2062.87 U1.10@2464.42,1947.17
  Signal Layer 1 w10: v3(2417.7,2094.66) 2417.93,2094.89 2417.93,2142.03 2495.23,2219.33 2495.23,2242.29 2557.56,2304.62 2557.56,2558.56 2868.51,2869.51 2868.51,3026.04 2892.47,3050 3200,3050 J14.1@3250,3000
CFG2: J8.1 R55.2 S1.9 S1.10 S1.11 S1.12 S1.13 S1.14 S1.15 S1.16 S2.9 S2.10 S2.11 S2.12 S2.13 S2.14 S2.15 S2.16 U1.8 | length 2064.1
  Top Layer w10: U1.8@2503.79,1947.17 2503.79,2023.26 2531.4,2050.87 R55.2@2531.4,2060.8 2531.4,2075.56 v1(2531.84,2076.01) ; v1(3280,2275) S1.9@3315,2275 ; J8.1@3318.61,2068.72 3318.61,2271.39 S1.9@3315,2275 ; S2.16@4165,2275 S2.15@4115,2275 S2.14@4065,2275 S2.13@4015,2275 S2.12@3965,2275 S2.11@3915,2275 S2.10@3865,2275 S2.9@3815,2275 S1.16@3665,2275 S1.15@3615,2275 S1.14@3565,2275 S1.13@3515,2275 S1.12@3465,2275 S1.11@3415,2275 S1.10@3365,2275 3318.61,2275 S1.9@3315,2275
  Signal Layer 1 w10: v1(2531.84,2076.01) 2662.84,2076.01 2678.13,2091.3 2693.8,2091.3 2694.08,2091.59 2811.39,2091.59 2811.67,2091.3 3040.23,2091.3 3223.93,2275 v1(3280,2275)
COMP: C43.1 R32.2 R68.2 TP13.1 U1.13 | length 469.3
  Top Layer w10: TP13.1@2333.66,2205.39 2333.66,2159.41 2362.19,2130.89 C43.1@2362.19,2097.1 R32.2@2362.19,2042.59 2362.19,2020.25 2396,1986.44 2396,1902.16 2415.94,1882.21 U1.13@2438.83,1882.21
  Bottom Layer w10: TP13.1@2333.66,2205.39 2344.05,2195 R68.2@2408,2195 v3@2418.56,2195
  other v3: 2418.56,2195.8
COMP1: D3.2 Q7.3 R66.1 R68.1 R74.1 | length 2832.4
  Signal Layer 1 w10: v3(3823.8,2495.58) 3823.8,2465.31 3896.94,2392.18 4481.92,2392.18 4651.74,2562 v1(4706.53,2562)
  Signal Layer 1 w20: v3(2698,2437.27) 2753.03,2437.27 2761.7,2428.6 v3(2765.48,2428.6)
  Signal Layer 2 w20: v3(2591.91,2196.5) 2686.12,2196.5 2698,2208.38 v3(2698,2437.27) ; v3(2765.48,2428.6) 2826.2,2489.32 3816.46,2489.32 3822.72,2495.58 v3(3823.8,2495.58)
  Bottom Layer w10: R68.1@2468,2195 2469.14,2196.14 v3@2591.91,2196.14 ; R74.1@3780.01,2555 R66.1@3780.01,2495.58 v3(3823.8,2495.58) ; R74.1@3784.01,2551 D3.2@3850.53,2551 ; Q7.3@4702.53,2588 4705.71,2584.82 4705.71,2562.82 v1(4706.53,2562)
CSA/SW1: C48.2 R7.1 U1.22 | length 352.4
  Top Layer w10: R7.1@2170,1670 2175,1675 2175,1686.27 2180.86,1692.13 2375,1692.13 2384.63,1682.5 2409,1682.5 2411.5,1680 2425.64,1694.14 2473.52,1694.14 2484.02,1704.65 U1.22@2484.02,1712.02
CSB: C48.1 R8.1 U1.21 | length 300.8
  Top Layer w10: R8.1@2168.96,1724.18 2168.96,1723.83 2173.96,1718.83 2240.84,1718.83 2244.4,1715.27 2380.12,1715.27 2382.35,1717.5 2403.67,1717.5 2405,1718.83 U1.21@2464.42,1718.83
DRV1: C88.1 J11.1 R38.1 U1.35 | length 2930.5
  Top Layer w10: v2@2710.88,1811.58 v2(2712.5,1811.58)
  Top Layer w12: U1.35@2667.17,1823.16 2699.3,1823.16 v2@2710.88,1811.58
  Signal Layer 2 w15: J11.1@813,1971.92 998.76,1971.92 1038.76,1931.92 1038.76,1740.92 v3(1052.31,1727.36)
  Bottom Layer w10: J11.1@813,1971.92 814.97,1969.94 814.97,1930.29 837.22,1908.04 848.6,1908.04 853.6,1903.04 C88.1@853.6,1895.71
  Bottom Layer w20: J11.1@813,1971.92 888.58,1971.92 1222.27,2305.61 2121.32,2305.61 2150.31,2276.63 2150.31,2168.23 2347.73,1970.81 2591.3,1970.81 2712.5,1849.61 v2(2712.5,1811.58)
DTRK: C54.1 R24.2 U1.4 | length 181.3
  Top Layer w10: U1.4@2582.53,1947.17 2582.53,1978.27 2619.5,2015.24 2619.5,2060.8 ; C54.1@2594.9,2060.8 2614.58,2060.8 2619.5,2060.8 ; R24.2@2647.23,2060.8 2619.5,2060.8
DTRK1: JP3.2 R24.1 | length 1990.6
  Top Layer w10: v1(2646.23,2102.84) 2647.23,2103.84 R24.1@2647.23,2120.8
  Signal Layer 1 w10: v1(2646.23,2102.84) 2665.26,2121.88 2665.26,2457.91 3098.37,2891.02 3941.02,2891.02 JP3.2@4050,3000
EN/UVLO: C47.1 R15.1 R16.1 R17.2 U1.37 | length 2733.7
  Top Layer w10: R15.1@960.36,2832.68 R17.2@1040.61,2832.68 ; U1.37@2667.17,1862.53 2703.21,1862.53 2714.33,1873.65 2764.9,1873.65 2777.98,1886.74 v1(2809.16,1886.74)
  Signal Layer 1 w8: v3(1000,2849.47) 1031.6,2849.47 1358.18,2522.88 1745.1,2522.88 2275.8,1992.18 2275.8,1876.98 2243.24,1844.42 2243.24,1823.81 2257.82,1809.24 2266.29,1809.24 2336.27,1739.27 2648.52,1739.27 2670.63,1761.38 2670.63,1806.97 2727.78,1864.12 2786.54,1864.12 v1(2809.16,1886.74)
FB: C50.2 C51.1 R18.1 R20.1 R21.2 U1.14 | length 424.8
  Top Layer w10: R18.1@2100.43,1999.98 C51.1@2153.05,1999.98 2153.48,2000.42 C50.2@2209.91,2000.42 R20.1@2266.51,2000.42 2266.96,2000.86 R21.2@2320.21,2000.86 2378.12,1942.95 2378.12,1893.95 2405,1867.07 2405.68,1867.07 2410.22,1862.53 U1.14@2438.83,1862.53
FLT: J9.1 R33.1 U1.11 | length 1515.7
  Top Layer w10: U1.11@2438.83,1921.58 v1(2438.83,2007.96) ; R33.1@2948.51,2793.22 2948.51,2998.51 J9.1@2950,3000
  Signal Layer 1 w10: v1(2438.83,2007.96) 2438.83,2008.78 2450.87,2020.82 2450.87,2055.47 2442.57,2063.76 2442.57,2137.09 2484.2,2178.71 2503.46,2178.71 2556.08,2231.33 2556.08,2247.84 2575.44,2267.19 2575.44,2548.27 2950,2922.83 J9.1@2950,3000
